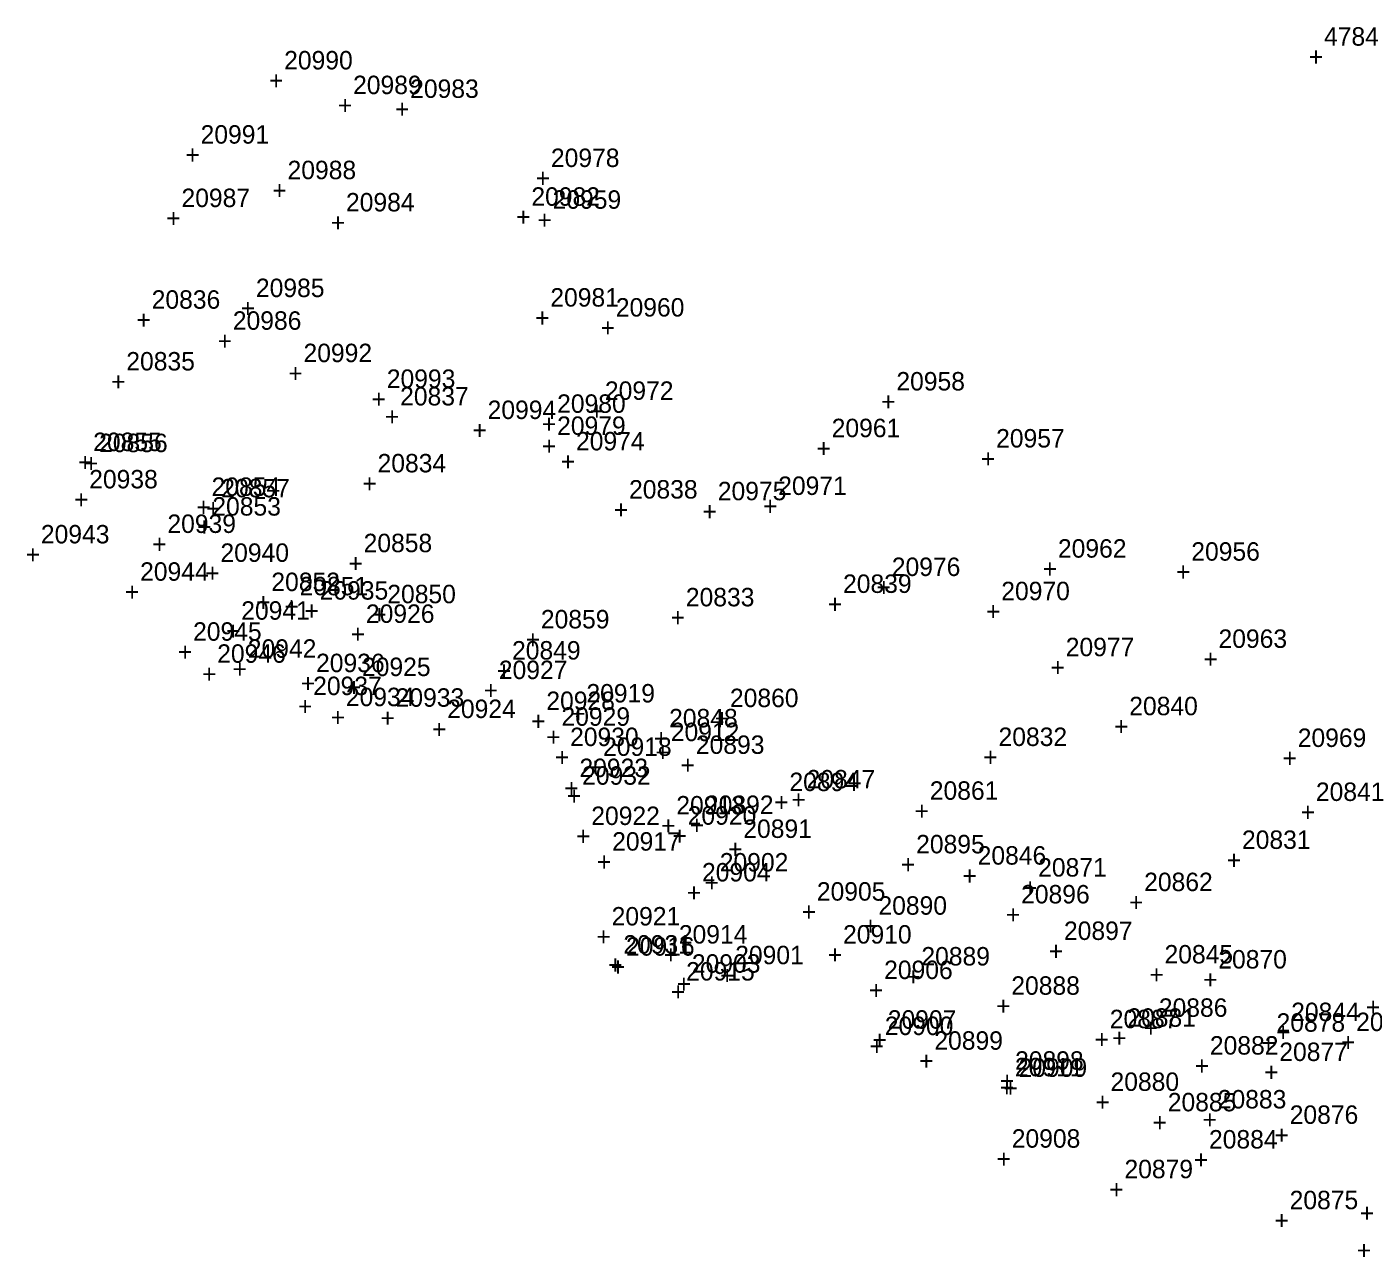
# Model space of a CAD drawing. Extents: x 1036751 to 1042192, y 772604 to 785439.
# Drawn here: x 1037491.3 to 1037673.8, y 780619.3 to 780786.1 of the extents above; entities that cross this region are included whole.
import ezdxf

# ---------------------------------------------------------------- set-up
doc = ezdxf.new("R2010")
doc.units = 0
for name, color, linetype in [('S_Buildings', 7, 'Continuous'), ('S_Buildings_SillElevation', 7, 'Continuous'), ('S_Ground_Elevation', 7, 'Continuous'), ('S_Ground_LevelString', 7, 'Continuous'), ('S_Property_IronPipeFound', 7, 'Continuous'), ('S_Roadway_Centerline', 7, 'Continuous'), ('S_Roadway_Edge_Pavement', 7, 'Continuous'), ('S_Roadway_Entr_Field_Wood', 7, 'Continuous'), ('S_Traffic_Sign_SinglePost', 7, 'Continuous'), ('S_Trees_Conifer_Pay', 7, 'Continuous'), ('S_Trees_TreeLine', 7, 'Continuous'), ('S_Utilities_Hydrant', 7, 'Continuous'), ('S_Utilities_Pole_Power', 7, 'Continuous')]:
    doc.layers.add(name, color=color, linetype=linetype)

msp = doc.modelspace()

# ---------------------------------------------------------------- texts
at = {"layer": 'S_Buildings'}
for s, p in [('20909', (1037625.72, 780643.76)), ('+', (1037623.66, 780641.01)), ('20908', (1037624.79, 780634.16)), ('+', (1037622.73, 780631.41))]:
    msp.add_text(s, height=2.5, dxfattribs=at).set_placement(p)
at = {"layer": 'S_Buildings_SillElevation'}
for s, p in [('20911', (1037625.22, 780643.84)), ('+', (1037623.16, 780641.09))]:
    msp.add_text(s, height=2.5, dxfattribs=at).set_placement(p)
at = {"layer": 'S_Ground_Elevation'}
for s, p in [('4784', (1037667.12, 780783.54)), ('20990', (1037526.16, 780780.32)), ('+', (1037665.06, 780780.79)), ('+', (1037524.1, 780777.57)), ('20989', (1037535.5, 780776.97)), ('+', (1037533.44, 780774.22)), ('20991', (1037514.83, 780770.26)), ('+', (1037512.77, 780767.51)), ('20988', (1037526.62, 780765.44)), ('20987', (1037512.24, 780761.66)), ('+', (1037524.55, 780762.69)), ('20959', (1037562.55, 780761.43)), ('+', (1037510.17, 780758.91)), ('+', (1037560.48, 780758.68)), ('20960', (1037571.12, 780746.82)), ('+', (1037569.06, 780744.07)), ('20972', (1037569.64, 780735.53)), ('+', (1037567.58, 780732.78)), ('20961', (1037600.38, 780730.47)), ('20974', (1037565.72, 780728.68)), ('+', (1037598.32, 780727.72)), ('+', (1037563.66, 780725.93)), ('20938', (1037499.73, 780723.53)), ('20971', (1037593.13, 780722.64)), ('+', (1037497.67, 780720.78)), ('20975', (1037584.94, 780721.92)), ('+', (1037582.87, 780719.17)), ('+', (1037591.07, 780719.89)), ('20939', (1037510.33, 780717.49)), ('20943', (1037493.18, 780716.07)), ('+', (1037508.27, 780714.74)), ('20940', (1037517.52, 780713.57)), ('20962', (1037631.05, 780714.14)), ('+', (1037491.12, 780713.32)), ('20976', (1037608.53, 780711.65)), ('20944', (1037506.63, 780711.01)), ('+', (1037515.46, 780710.82)), ('+', (1037628.99, 780711.39)), ('+', (1037504.57, 780708.26)), ('20935', (1037530.97, 780708.45)), ('+', (1037606.47, 780708.9)), ('20970', (1037623.37, 780708.37)), ('20941', (1037520.34, 780705.73)), ('+', (1037528.91, 780705.7)), ('20926', (1037537.24, 780705.3)), ('+', (1037621.31, 780705.62)), ('20945', (1037513.81, 780702.88)), ('+', (1037518.28, 780702.98)), ('+', (1037535.18, 780702.55)), ('20942', (1037521.23, 780700.57)), ('20977', (1037632.11, 780700.78)), ('20963', (1037652.82, 780701.91)), ('+', (1037511.75, 780700.13)), ('20946', (1037517.08, 780699.89)), ('20936', (1037530.48, 780698.62)), ('+', (1037650.76, 780699.16)), ('+', (1037515.02, 780697.14)), ('+', (1037519.17, 780697.82)), ('20925', (1037536.71, 780698.09)), ('20927', (1037555.26, 780697.68)), ('+', (1037630.05, 780698.03)), ('+', (1037528.42, 780695.87)), ('20937', (1037530.09, 780695.51)), ('+', (1037534.65, 780695.34)), ('+', (1037553.2, 780694.93)), ('20928', (1037561.7, 780693.49)), ('+', (1037528.03, 780692.76)), ('20924', (1037548.26, 780692.4)), ('20929', (1037563.75, 780691.35)), ('+', (1037559.64, 780690.74)), ('+', (1037546.2, 780689.65)), ('+', (1037561.69, 780688.6)), ('20930', (1037564.92, 780688.6)), ('20893', (1037581.97, 780687.54)), ('20969', (1037663.56, 780688.48)), ('+', (1037562.86, 780685.85)), ('20923', (1037566.19, 780684.4)), ('+', (1037579.9, 780684.79)), ('+', (1037661.5, 780685.73)), ('20894', (1037594.65, 780682.5)), ('+', (1037564.13, 780681.65)), ('20892', (1037583.2, 780679.4)), ('+', (1037592.59, 780679.75)), ('20922', (1037567.79, 780677.9)), ('+', (1037565.73, 780675.15)), ('+', (1037581.14, 780676.65)), ('20891', (1037588.4, 780676.15)), ('+', (1037586.34, 780673.4)), ('20895', (1037611.83, 780674.06)), ('20902', (1037585.21, 780671.6)), ('+', (1037609.77, 780671.31)), ('+', (1037583.15, 780668.85)), ('20890', (1037606.72, 780665.74)), ('20896', (1037626.06, 780667.27)), ('20921', (1037570.55, 780664.28)), ('+', (1037624, 780664.52)), ('+', (1037604.66, 780662.99)), ('20897', (1037631.87, 780662.32)), ('+', (1037568.48, 780661.53)), ('20901', (1037587.3, 780659.03)), ('20889', (1037612.54, 780658.86)), ('+', (1037629.81, 780659.57)), ('+', (1037585.24, 780656.28)), ('+', (1037610.48, 780656.11)), ('20888', (1037624.73, 780654.89)), ('+', (1037622.67, 780652.14)), ('20900', (1037607.58, 780649.43)), ('20887', (1037638.08, 780650.36)), ('20881', (1037640.46, 780650.55)), ('20878', (1037660.69, 780649.88)), ('20899', (1037614.3, 780647.44)), ('+', (1037638.4, 780647.8)), ('+', (1037605.52, 780646.68)), ('+', (1037636.02, 780647.61)), ('20882', (1037651.65, 780646.78)), ('+', (1037658.63, 780647.13)), ('20877', (1037661.06, 780645.91)), ('+', (1037612.24, 780644.69)), ('20898', (1037625.24, 780644.73)), ('20880', (1037638.18, 780641.86)), ('+', (1037649.59, 780644.03)), ('+', (1037659, 780643.16)), ('+', (1037623.18, 780641.98)), ('+', (1037636.12, 780639.11)), ('20883', (1037652.72, 780639.48)), ('20876', (1037662.47, 780637.39)), ('+', (1037650.66, 780636.73)), ('20884', (1037651.53, 780634.05)), ('+', (1037660.41, 780634.64)), ('20879', (1037640.07, 780630.02)), ('+', (1037649.47, 780631.3)), ('+', (1037638.01, 780627.27)), ('20875', (1037662.46, 780625.82)), ('+', (1037671.97, 780624.07)), ('+', (1037660.4, 780623.07)), ('+', (1037671.56, 780619.02))]:
    msp.add_text(s, height=2.5, dxfattribs=at).set_placement(p)
at = {"layer": 'S_Ground_LevelString'}
for s, p in [('20992', (1037528.78, 780740.64)), ('+', (1037526.72, 780737.89)), ('20993', (1037540.07, 780737.15)), ('+', (1037538.01, 780734.4)), ('20994', (1037553.74, 780732.93)), ('+', (1037551.68, 780730.18)), ('20857', (1037517.63, 780722.32)), ('+', (1037515.57, 780719.57)), ('20858', (1037536.93, 780714.88)), ('+', (1037534.87, 780712.13)), ('20859', (1037560.96, 780704.55)), ('+', (1037558.9, 780701.8)), ('20860', (1037586.59, 780693.88)), ('+', (1037584.53, 780691.13)), ('20861', (1037613.68, 780681.32)), ('+', (1037611.62, 780678.57)), ('20871', (1037628.37, 780670.91)), ('+', (1037626.31, 780668.16)), ('20862', (1037642.74, 780668.94)), ('+', (1037640.68, 780666.19)), ('20870', (1037652.79, 780658.45)), ('+', (1037650.73, 780655.7)), ('+', (1037672.8, 780651.99)), ('20869', (1037671.48, 780649.97)), ('+', (1037669.42, 780647.22))]:
    msp.add_text(s, height=2.5, dxfattribs=at).set_placement(p)
at = {"layer": 'S_Property_IronPipeFound'}
for s, p in [('20910', (1037601.92, 780661.83)), ('+', (1037599.86, 780659.08))]:
    msp.add_text(s, height=2.5, dxfattribs=at).set_placement(p)
at = {"layer": 'S_Roadway_Centerline'}
for s, p in [('20835', (1037504.76, 780739.51)), ('+', (1037502.7, 780736.76)), ('20834', (1037538.82, 780725.7)), ('+', (1037536.76, 780722.95)), ('20833', (1037580.61, 780707.54)), ('+', (1037578.55, 780704.79)), ('20832', (1037623, 780688.61)), ('+', (1037620.93, 780685.86)), ('20831', (1037656, 780674.66)), ('+', (1037653.94, 780671.91))]:
    msp.add_text(s, height=2.5, dxfattribs=at).set_placement(p)
at = {"layer": 'S_Roadway_Edge_Pavement'}
for s, p in [('20836', (1037508.2, 780747.88)), ('+', (1037506.14, 780745.13)), ('20837', (1037541.88, 780734.77)), ('+', (1037539.82, 780732.02)), ('20855', (1037500.27, 780728.59)), ('20856', (1037501.07, 780728.44)), ('+', (1037498.21, 780725.84)), ('+', (1037499.01, 780725.69)), ('20854', (1037516.32, 780722.51)), ('20838', (1037572.91, 780722.15)), ('+', (1037514.26, 780719.76)), ('20853', (1037516.42, 780719.84)), ('+', (1037570.85, 780719.4)), ('+', (1037514.36, 780717.09)), ('20852', (1037524.42, 780709.61)), ('20839', (1037601.92, 780709.36)), ('20851', (1037528.25, 780709.04)), ('20850', (1037540.14, 780707.96)), ('+', (1037522.36, 780706.86)), ('+', (1037526.19, 780706.29)), ('+', (1037599.86, 780706.61)), ('+', (1037538.08, 780705.21)), ('20849', (1037557.05, 780700.33)), ('+', (1037554.99, 780697.58)), ('20848', (1037578.34, 780691.14)), ('20840', (1037640.72, 780692.78)), ('+', (1037638.66, 780690.03)), ('+', (1037576.28, 780688.39)), ('20847', (1037596.98, 780682.86)), ('20841', (1037666.02, 780681.16)), ('+', (1037594.92, 780680.11)), ('+', (1037663.96, 780678.41)), ('20846', (1037620.17, 780672.53)), ('+', (1037618.11, 780669.78)), ('20845', (1037645.5, 780659.13)), ('+', (1037643.44, 780656.38)), ('20844', (1037662.67, 780651.32)), ('+', (1037660.61, 780648.57))]:
    msp.add_text(s, height=2.5, dxfattribs=at).set_placement(p)
at = {"layer": 'S_Roadway_Entr_Field_Wood'}
for s, p in [('20983', (1037543.24, 780776.46)), ('+', (1037541.18, 780773.71)), ('20984', (1037534.54, 780761.07)), ('20982', (1037559.67, 780761.84)), ('+', (1037557.61, 780759.09)), ('+', (1037532.48, 780758.32)), ('20985', (1037522.33, 780749.46)), ('20981', (1037562.24, 780748.17)), ('+', (1037520.26, 780746.71)), ('20986', (1037519.2, 780745.03)), ('+', (1037560.18, 780745.42)), ('+', (1037517.14, 780742.28)), ('20980', (1037563.16, 780733.77)), ('+', (1037561.09, 780731.02)), ('20979', (1037563.16, 780730.78)), ('+', (1037561.1, 780728.03)), ('20919', (1037567.13, 780694.51)), ('+', (1037565.07, 780691.76)), ('20912', (1037578.57, 780689.27)), ('20918', (1037569.39, 780687.27)), ('+', (1037576.51, 780686.52)), ('+', (1037567.33, 780684.52)), ('20913', (1037579.32, 780679.33)), ('+', (1037577.26, 780676.58)), ('20917', (1037570.62, 780674.43)), ('+', (1037568.56, 780671.68)), ('20916', (1037572.5, 780660.19)), ('20914', (1037579.66, 780661.83)), ('+', (1037577.6, 780659.08)), ('+', (1037570.44, 780657.45)), ('20915', (1037580.65, 780656.82)), ('+', (1037578.58, 780654.07))]:
    msp.add_text(s, height=2.5, dxfattribs=at).set_placement(p)
at = {"layer": 'S_Traffic_Sign_SinglePost'}
for s, p in [('20920', (1037580.86, 780677.94)), ('+', (1037578.8, 780675.19))]:
    msp.add_text(s, height=2.5, dxfattribs=at).set_placement(p)
at = {"layer": 'S_Trees_Conifer_Pay'}
for s, p in [('20885', (1037645.94, 780639.09)), ('+', (1037643.88, 780636.34))]:
    msp.add_text(s, height=2.5, dxfattribs=at).set_placement(p)
at = {"layer": 'S_Trees_TreeLine'}
for s, p in [('20958', (1037609.15, 780736.8)), ('+', (1037607.09, 780734.05)), ('20957', (1037622.67, 780729.07)), ('+', (1037620.61, 780726.32)), ('20956', (1037649.13, 780713.73)), ('+', (1037647.06, 780710.98)), ('20934', (1037534.52, 780694.01)), ('20933', (1037541.27, 780693.93)), ('+', (1037532.46, 780691.26)), ('+', (1037539.21, 780691.18)), ('20932', (1037566.55, 780683.36)), ('+', (1037564.49, 780680.61)), ('20904', (1037582.8, 780670.25)), ('20905', (1037598.37, 780667.65)), ('+', (1037580.74, 780667.5)), ('+', (1037596.31, 780664.9)), ('20931', (1037572.14, 780660.47)), ('+', (1037570.08, 780657.72)), ('20903', (1037581.43, 780657.88)), ('20906', (1037607.49, 780657.02)), ('+', (1037579.37, 780655.13)), ('+', (1037605.43, 780654.27)), ('20907', (1037607.98, 780650.29)), ('+', (1037605.91, 780647.54))]:
    msp.add_text(s, height=2.5, dxfattribs=at).set_placement(p)
at = {"layer": 'S_Utilities_Hydrant'}
for s, p in [('20886', (1037644.73, 780651.9)), ('+', (1037642.67, 780649.15))]:
    msp.add_text(s, height=2.5, dxfattribs=at).set_placement(p)
at = {"layer": 'S_Utilities_Pole_Power'}
for s, p in [('20978', (1037562.32, 780767.09)), ('+', (1037560.26, 780764.34))]:
    msp.add_text(s, height=2.5, dxfattribs=at).set_placement(p)

doc.saveas('drawing.dxf')
